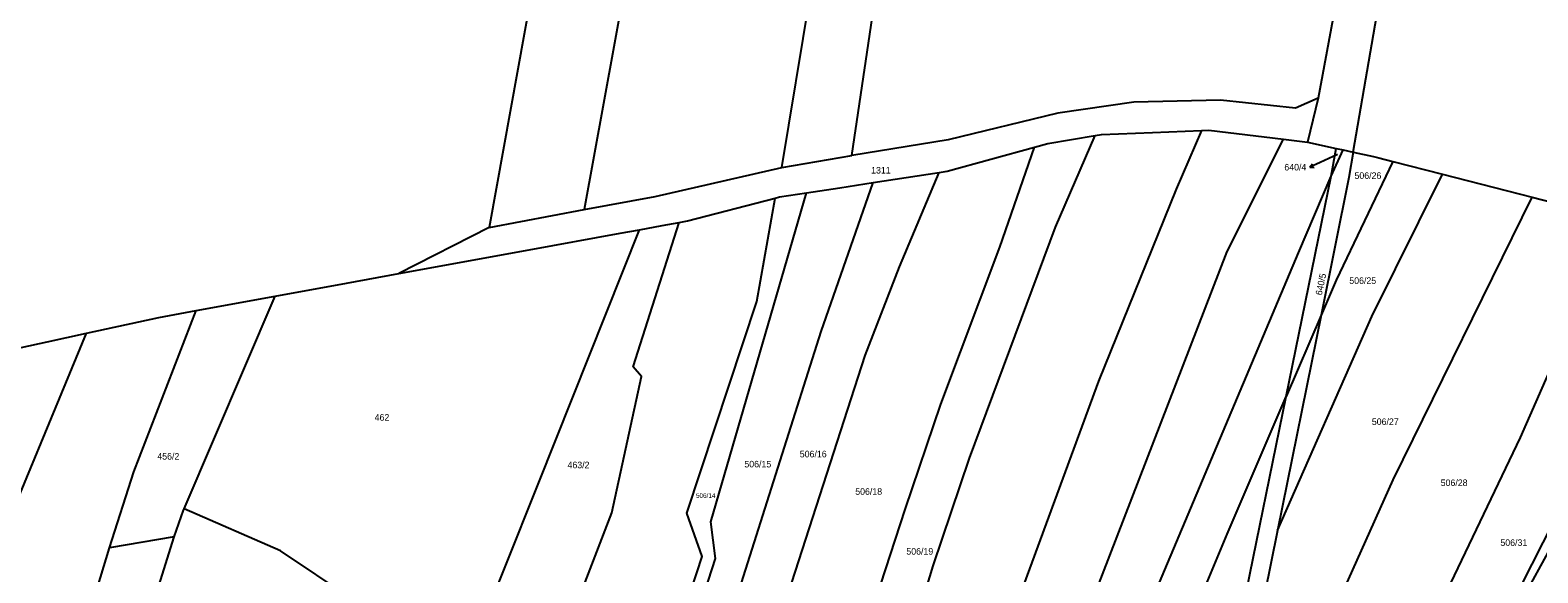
# Model space of a CAD drawing. Extents: x -746176 to -739709, y -1128407 to -1124482.
# Drawn here: x -742864.4 to -742474.2, y -1126882.3 to -1126742 of the extents above; entities that cross this region are included whole.
import ezdxf

# ---------------------------------------------------------------- set-up
doc = ezdxf.new("R2010")
doc.units = 0
for name, color, linetype in [('Vrstva 33', 7, 'Continuous'), ('Vrstva 42', 7, 'Continuous'), ('Vrstva 43', 7, 'Continuous')]:
    doc.layers.add(name, color=color, linetype=linetype)

msp = doc.modelspace()

# ---------------------------------------------------------------- linework, layer by layer
at = {"layer": 'Vrstva 33'}
for p, q in [((-742669.88, -1126777.52), (-742639.25, -1126591.77)), ((-742531.03, -1126759.57), (-742533.77, -1126770.91)), ((-742540.06, -1126770.15), (-742533.77, -1126770.91)), ((-742540.06, -1126770.15), (-742533.77, -1126770.91)), ((-742533.77, -1126770.91), (-742526.41, -1126772.54)), ((-742533.77, -1126770.91), (-742526.41, -1126772.54)), ((-742669.88, -1126777.52), (-742651.76, -1126774.43)), ((-742527.67, -1126779.74), (-742526.41, -1126772.54)), ((-742527.67, -1126779.74), (-742524.54, -1126772.95)), ((-742526.41, -1126772.54), (-742524.54, -1126772.95)), ((-742526.41, -1126772.54), (-742524.54, -1126772.95)), ((-742524.54, -1126772.95), (-742521.95, -1126773.52)), ((-742524.54, -1126772.95), (-742521.95, -1126773.52)), ((-742646.21, -1126781.41), (-742629.18, -1126778.81)), ((-742646.21, -1126781.41), (-742629.18, -1126778.81)), ((-742511.74, -1126775.91), (-742498.85, -1126779.22)), ((-742511.74, -1126775.91), (-742498.85, -1126779.22)), ((-742498.85, -1126779.22), (-742475.66, -1126785.18)), ((-742498.85, -1126779.22), (-742475.66, -1126785.18)), ((-742539.32, -1126836.74), (-742527.67, -1126779.74)), ((-742475.66, -1126785.18), (-742451.42, -1126791.4)), ((-742475.66, -1126785.18), (-742451.42, -1126791.4)), ((-742745.64, -1126793.01), (-742721.02, -1126788.32)), ((-742745.64, -1126793.01), (-742769.01, -1126804.93)), ((-742706.72, -1126793.58), (-742700.87, -1126792.51)), ((-742706.72, -1126793.58), (-742700.87, -1126792.51)), ((-742700.87, -1126792.51), (-742696.43, -1126791.7)), ((-742700.87, -1126792.51), (-742696.43, -1126791.7)), ((-742824.58, -1126865.74), (-742800.98, -1126810.76)), ((-742821.45, -1126814.49), (-742800.98, -1126810.76)), ((-742821.45, -1126814.49), (-742800.98, -1126810.76)), ((-742530.29, -1126815.68), (-742541.56, -1126871.36)), ((-742530.29, -1126815.68), (-742539.32, -1126836.74)), ((-742550.57, -1126891.8), (-742539.32, -1126836.74)), ((-742465.86, -1126866.52), (-742477.38, -1126887.58)), ((-742827.15, -1126873), (-742843.85, -1126875.84)), ((-742838.1, -1126908.15), (-742827.15, -1126873)), ((-742851.71, -1126901.51), (-742843.85, -1126875.84))]:
    msp.add_line(p, q, dxfattribs=at)
for points in [[(-742521.95, -1126773.52), (-742504.56, -1126672.68), (-742497, -1126628.23), (-742488.98, -1126567.9), (-742478.35, -1126466.13), (-742467.6, -1126363.23), (-742463.32, -1126296.13), (-742459.73, -1126263.65), (-742452.82, -1126263.88), (-742450.23, -1126260.63), (-742452.38, -1126257.65), (-742458.75, -1126256.81), (-742455.22, -1126201.03)], [(-742482.39, -1126414.71), (-742498.43, -1126567.43), (-742506.05, -1126624.82), (-742531.03, -1126759.57)], [(-742684.93, -1126590.96), (-742709.04, -1126591.22), (-742727.32, -1126691.99), (-742745.64, -1126793.01)], [(-742684.93, -1126590.96), (-742703.12, -1126690.44), (-742721.02, -1126788.32)], [(-742651.76, -1126774.43), (-742624.84, -1126593.06), (-742639.25, -1126591.77)], [(-742531.03, -1126759.57), (-742536.88, -1126762.13), (-742556.33, -1126760.06), (-742578.73, -1126760.64), (-742598.4, -1126763.45), (-742626.82, -1126770.34), (-742651.76, -1126774.43)], [(-742679.87, -1127010.3), (-742661.43, -1126968.75), (-742645.29, -1126928.59), (-742630.66, -1126880.5), (-742621.29, -1126852.62), (-742599.04, -1126792.93), (-742588.76, -1126769.25)], [(-742561.23, -1126767.89), (-742567.77, -1126783.13), (-742587.89, -1126832.72), (-742634.42, -1126959.12), (-742661.75, -1127022.4)], [(-742648.95, -1127033.28), (-742621.1, -1126971.78), (-742603.91, -1126926.94), (-742554.63, -1126799.18), (-742540.06, -1126770.15)], [(-742604.44, -1126772.24), (-742601.05, -1126771.3), (-742588.76, -1126769.25)], [(-742604.44, -1126772.24), (-742601.05, -1126771.3), (-742588.76, -1126769.25)], [(-742588.76, -1126769.25), (-742587.09, -1126768.97), (-742573.9, -1126768.42), (-742561.23, -1126767.89)], [(-742588.76, -1126769.25), (-742587.09, -1126768.97), (-742573.9, -1126768.42), (-742561.23, -1126767.89)], [(-742561.23, -1126767.89), (-742559.37, -1126767.81), (-742540.06, -1126770.15)], [(-742561.23, -1126767.89), (-742559.37, -1126767.81), (-742540.06, -1126770.15)], [(-742688.81, -1127002.53), (-742675.39, -1126975.35), (-742650.59, -1126904.79), (-742637.92, -1126865.97), (-742628.71, -1126838.73), (-742613.44, -1126798.13), (-742604.44, -1126772.24)], [(-742629.18, -1126778.81), (-742627.56, -1126778.56), (-742627.03, -1126778.48), (-742604.44, -1126772.24)], [(-742629.18, -1126778.81), (-742627.56, -1126778.56), (-742627.03, -1126778.48), (-742604.44, -1126772.24)], [(-742521.95, -1126773.52), (-742523.09, -1126780.11), (-742530.29, -1126815.68)], [(-742521.95, -1126773.52), (-742516.73, -1126774.67), (-742515.35, -1126774.98), (-742511.74, -1126775.91)], [(-742521.95, -1126773.52), (-742516.73, -1126774.67), (-742515.35, -1126774.98), (-742511.74, -1126775.91)], [(-742721.02, -1126788.32), (-742702.6, -1126784.99), (-742669.88, -1126777.52)], [(-742703.1, -1126987.76), (-742688.91, -1126951.77), (-742648.33, -1126826.13), (-742639.39, -1126803.22), (-742629.18, -1126778.81)], [(-742541.56, -1126871.36), (-742517.16, -1126816.01), (-742498.85, -1126779.22)], [(-742511.74, -1126775.91), (-742526.39, -1126806.59), (-742530.29, -1126815.68)], [(-742710.71, -1126977.95), (-742691.49, -1126920.27), (-742659.71, -1126819.94), (-742646.21, -1126781.41)], [(-742663.45, -1126784.04), (-742654.84, -1126782.73), (-742646.21, -1126781.41)], [(-742663.45, -1126784.04), (-742654.84, -1126782.73), (-742646.21, -1126781.41)], [(-742638.43, -1127039.61), (-742614.56, -1126990.57), (-742601.46, -1126960.43), (-742573.73, -1126888.65), (-742536.1, -1126799.53), (-742527.67, -1126779.74)], [(-742719.6, -1126967.23), (-742690.51, -1126878.08), (-742694.48, -1126866.91), (-742676.36, -1126812.17), (-742671.59, -1126785.41)], [(-742716.17, -1126970.68), (-742712.23, -1126956.56), (-742687.03, -1126878.58), (-742688.27, -1126869.14), (-742663.45, -1126784.04)], [(-742696.43, -1126791.7), (-742694.29, -1126791.31), (-742671.59, -1126785.41)], [(-742696.43, -1126791.7), (-742694.29, -1126791.31), (-742671.59, -1126785.41)], [(-742671.59, -1126785.41), (-742670.45, -1126785.11), (-742665.8, -1126784.4), (-742663.45, -1126784.04)], [(-742671.59, -1126785.41), (-742670.45, -1126785.11), (-742665.8, -1126784.4), (-742663.45, -1126784.04)], [(-742562.72, -1126972.14), (-742511.64, -1126858.28), (-742475.66, -1126785.18)], [(-742769.01, -1126804.93), (-742735.24, -1126798.77), (-742711.7, -1126794.48), (-742706.72, -1126793.58)], [(-742769.01, -1126804.93), (-742735.24, -1126798.77), (-742711.7, -1126794.48), (-742706.72, -1126793.58)], [(-742750.49, -1126903.46), (-742732.76, -1126858.93), (-742706.72, -1126793.58)], [(-742730.7, -1126910.48), (-742713.83, -1126866.81), (-742706.14, -1126831.54), (-742708.37, -1126829.06), (-742696.43, -1126791.7)], [(-742576.22, -1127042.62), (-742572.46, -1127037.81), (-742549.96, -1126996.44), (-742502.42, -1126896.85), (-742478.65, -1126847.35), (-742462.47, -1126810.41), (-742451.42, -1126791.4)], [(-742431.72, -1126796.46), (-742469.95, -1126868.69), (-742501.91, -1126931.51), (-742517.1, -1126960.81), (-742540.36, -1126998.76), (-742553.75, -1127021.53), (-742568.92, -1127039.08), (-742575.31, -1127045.24)], [(-742800.98, -1126810.76), (-742782.52, -1126807.39), (-742769.01, -1126804.93)], [(-742800.98, -1126810.76), (-742782.52, -1126807.39), (-742769.01, -1126804.93)], [(-742849.79, -1126820.34), (-742831.12, -1126816.25), (-742821.45, -1126814.49)], [(-742849.79, -1126820.34), (-742831.12, -1126816.25), (-742821.45, -1126814.49)], [(-742843.85, -1126875.84), (-742837.53, -1126856.16), (-742821.45, -1126814.49)], [(-742967.31, -1127123.32), (-742948.78, -1127069.51), (-742913.81, -1126980), (-742891.52, -1126923.09), (-742875.03, -1126881.03), (-742849.79, -1126820.34)], [(-742866.72, -1126824.05), (-742859.97, -1126822.57), (-742849.79, -1126820.34)], [(-742866.72, -1126824.05), (-742859.97, -1126822.57), (-742849.79, -1126820.34)], [(-742629.44, -1127044.36), (-742612.06, -1127010.59), (-742600.55, -1126985.29), (-742577.05, -1126926.06), (-742554.59, -1126872.35), (-742539.32, -1126836.74)], [(-742827.15, -1126873), (-742824.73, -1126866.08), (-742824.58, -1126865.74)], [(-742750.49, -1126903.46), (-742763.27, -1126898.97), (-742762.5, -1126896.14), (-742781.04, -1126889), (-742799.57, -1126876.62), (-742824.58, -1126865.74)], [(-742541.56, -1126871.36), (-742553.22, -1126928.98), (-742562.72, -1126972.14)]]:
    msp.add_lwpolyline(points, dxfattribs=at)
at = {"layer": 'Vrstva 43'}
for p, q in [((-742526.01, -1126774.1), (-742530.52, -1126776.16)), ((-742530.52, -1126776.16), (-742533.24, -1126777.43)), ((-742533.24, -1126777.43), (-742532.54, -1126776.55)), ((-742533.24, -1126777.43), (-742532.12, -1126777.46))]:
    msp.add_line(p, q, dxfattribs=at)

# ---------------------------------------------------------------- texts
at = {"layer": 'Vrstva 42'}
for s, height, p in [('1311', 1.7, (-742646.74, -1126779.05)), ('640/4', 1.7, (-742539.8, -1126778.26)), ('506/26', 1.7, (-742521.65, -1126780.44)), ('506/25', 1.7, (-742522.99, -1126807.6)), ('462', 1.7, (-742775.24, -1126842.96)), ('506/27', 1.7, (-742517.16, -1126844.08)), ('456/2', 1.7, (-742831.49, -1126853.03)), ('463/2', 1.7, (-742725.32, -1126855.26)), ('506/15', 1.7, (-742679.55, -1126855.05)), ('506/16', 1.7, (-742665.21, -1126852.44)), ('506/18', 1.7, (-742650.86, -1126862.13)), ('506/28', 1.7, (-742499.34, -1126859.87)), ('506/14', 1.19, (-742692.07, -1126862.93)), ('506/19', 1.7, (-742637.63, -1126877.61)), ('506/31', 1.7, (-742483.88, -1126875.35))]:
    msp.add_text(s, height=height, dxfattribs=at).set_placement(p)
msp.add_text('640/5', height=1.7, rotation=78, dxfattribs=at).set_placement((-742530.11, -1126810.64))

doc.saveas('drawing.dxf')
